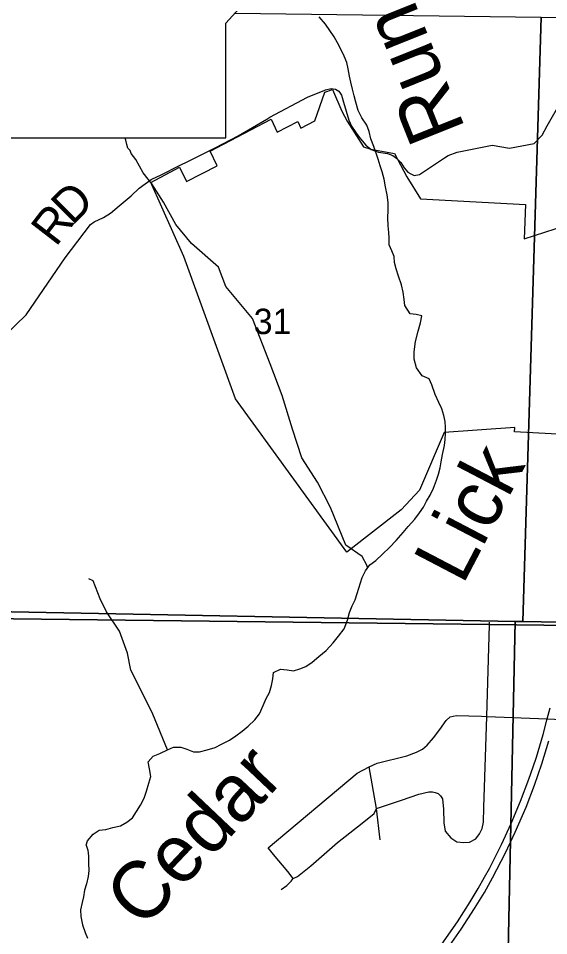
# Model space of a CAD drawing. Extents: x -19 to 40.8, y -1.8 to 26.1.
# Drawn here: x 4.466 to 5.34, y 15.443 to 16.956 of the extents above; entities that cross this region are included whole.
import ezdxf

# ---------------------------------------------------------------- set-up
doc = ezdxf.new("R2010")
doc.units = 0
for name, color, linetype in [('GM_X_City_Street', 7, 'Continuous'), ('GM_X_Corporation', 7, 'Continuous'), ('GM_X_County_Road_Text', 7, 'Continuous'), ('GM_X_Minor_River', 7, 'Continuous'), ('GM_X_Section', 7, 'Continuous'), ('GM_X_Section_Text', 7, 'Continuous'), ('GM_X_State_Route', 7, 'Continuous'), ('GM_X_Township_Road', 7, 'Continuous'), ('RW_P_Text', 7, 'Continuous'), ('SH_Text', 7, 'Continuous')]:
    doc.layers.add(name, color=color, linetype=linetype)

msp = doc.modelspace()

# ---------------------------------------------------------------- linework, layer by layer
at = {"layer": 'GM_X_City_Street'}
msp.add_lwpolyline([(5.4141, 16.267), (5.2834, 16.2739), (5.2839, 16.2809), (5.1674, 16.2728), (5.1269, 16.1777), (5.0969, 16.1455), (5.0073, 16.0756), (4.8238, 16.3283), (4.7384, 16.5632), (4.6842, 16.685), (4.7314, 16.7102), (4.7428, 16.6869), (4.7934, 16.7126), (4.7816, 16.7369), (4.8822, 16.7894), (4.8925, 16.7683), (4.9263, 16.7854), (4.9314, 16.7749), (4.9546, 16.7867), (4.9709, 16.8339), (4.9836, 16.8383), (4.9988, 16.8026), (5.0076, 16.786), (5.0348, 16.7441), (5.0466, 16.7398), (5.0857, 16.7329), (5.1062, 16.6943), (5.1288, 16.658), (5.3017, 16.6488), (5.2997, 16.5919), (5.6233, 16.6968)], dxfattribs=at)
at = {"layer": 'GM_X_Corporation'}
for points in [[(5.1684, 16.7259), (5.174, 16.7296), (5.1888, 16.7352), (5.2467, 16.7465), (5.2754, 16.7419), (5.3158, 16.7491), (5.329, 16.7629), (5.3375, 16.7783), (5.3827, 16.8572), (5.4132, 16.9039), (5.4201, 16.9126), (5.4273, 16.9192), (5.4375, 16.9273), (5.4465, 16.9319)], [(4.8753, 16.7896), (4.8803, 16.7926), (4.9421, 16.8259), (4.9708, 16.8374)], [(4.9708, 16.8374), (4.9717, 16.8378), (4.9812, 16.8399), (4.9883, 16.8389), (4.994, 16.8357), (4.9981, 16.8291), (5.0019, 16.8176), (5.0058, 16.8028), (5.0106, 16.7879), (5.0147, 16.7779), (5.0209, 16.769)], [(4.7898, 16.7422), (4.8282, 16.7618), (4.8753, 16.7896)], [(5.0209, 16.769), (5.0226, 16.7666), (5.0294, 16.7571), (5.0384, 16.7464), (5.0473, 16.7396), (5.0594, 16.7351), (5.0744, 16.7328), (5.0831, 16.7296), (5.0897, 16.7249), (5.0963, 16.7178), (5.1016, 16.7093), (5.1078, 16.7023), (5.1125, 16.6993), (5.118, 16.6968), (5.1271, 16.6983), (5.1684, 16.7259)], [(4.7463, 16.7203), (4.7801, 16.7373), (4.7898, 16.7422)], [(4.6854, 16.6904), (4.7008, 16.6979), (4.7315, 16.7129), (4.7463, 16.7203)], [(4.322, 16.3734), (4.3339, 16.3753), (4.3577, 16.3797), (4.3706, 16.3834), (4.3855, 16.3895), (4.4057, 16.4008), (4.4252, 16.4157), (4.4782, 16.4668), (4.5425, 16.5606), (4.5843, 16.6158), (4.5904, 16.6203), (4.6059, 16.6276), (4.6175, 16.6345), (4.6319, 16.6465), (4.6514, 16.663), (4.6648, 16.6758), (4.6846, 16.69), (4.6854, 16.6904)]]:
    msp.add_lwpolyline(points, dxfattribs=at)
at = {"layer": 'GM_X_Section'}
for points in [[(5.1001, 16.5044), (5.0974, 16.5164), (5.0924, 16.5304), (5.0882, 16.5428), (5.0856, 16.5533), (5.0849, 16.5628), (5.0812, 16.5726), (5.0767, 16.5823), (5.0767, 16.593), (5.0761, 16.6025), (5.0753, 16.6135), (5.0749, 16.6271), (5.0753, 16.6389), (5.0753, 16.6519), (5.0737, 16.6647), (5.071, 16.678), (5.0687, 16.6908), (5.0653, 16.7029), (5.062, 16.7127), (5.0589, 16.7236), (5.0514, 16.7446), (5.0469, 16.7571), (5.0438, 16.7691), (5.0401, 16.7796), (5.0317, 16.7919), (5.0256, 16.8039), (5.0222, 16.8175), (5.0192, 16.828), (5.0165, 16.839), (5.0139, 16.8503), (5.0113, 16.8605), (5.0094, 16.8726), (5.0072, 16.8828), (5.0027, 16.8933), (4.997, 16.9049), (4.9917, 16.9154), (4.9861, 16.9251), (4.9793, 16.9355), (4.9717, 16.9463), (4.9615, 16.9582)], [(5.0414, 16.0498), (5.0404, 16.0529), (5.0322, 16.0684), (5.0054, 16.0873), (4.9801, 16.1492), (4.9589, 16.191), (4.9332, 16.2313), (4.9176, 16.2785), (4.9004, 16.3337), (4.8806, 16.3858), (4.8516, 16.4606), (4.8076, 16.5135), (4.7953, 16.5452), (4.7508, 16.5847), (4.7252, 16.6158), (4.7046, 16.6527), (4.6855, 16.6828), (4.6712, 16.7012), (4.6594, 16.723), (4.6513, 16.7328), (4.6497, 16.7377), (4.6463, 16.7418), (4.6446, 16.7475), (4.6426, 16.7547), (4.6415, 16.7589)], [(4.5773, 15.5924), (4.5795, 15.5994), (4.5887, 15.6104), (4.5987, 15.6168), (4.6097, 15.6183), (4.6214, 15.6213), (4.6339, 15.6243), (4.6443, 15.63), (4.654, 15.6375), (4.6605, 15.6476), (4.667, 15.6581), (4.6731, 15.6697), (4.6769, 15.6816), (4.6807, 15.6943), (4.6842, 15.7058), (4.6819, 15.7182), (4.6796, 15.7296), (4.688, 15.7393), (4.6986, 15.7435), (4.7117, 15.7496), (4.7214, 15.7537), (4.7336, 15.7541), (4.7432, 15.7506), (4.7543, 15.7464), (4.7642, 15.7463), (4.7771, 15.7498), (4.7902, 15.7536), (4.8007, 15.7589), (4.8134, 15.7657), (4.8239, 15.7725), (4.8343, 15.7805), (4.8446, 15.7888), (4.8557, 15.799), (4.863, 15.8091), (4.869, 15.8226), (4.8744, 15.8342), (4.8794, 15.8442), (4.8828, 15.8557), (4.8851, 15.8668), (4.886, 15.8768), (4.8976, 15.8828), (4.9086, 15.8816), (4.9193, 15.8797), (4.9295, 15.8831), (4.9393, 15.8872), (4.9497, 15.894), (4.9612, 15.9035), (4.973, 15.9133), (4.9848, 15.9259), (4.9936, 15.9368), (5.0027, 15.9489), (5.008, 15.9631), (5.0114, 15.9758), (5.016, 15.9869), (5.0206, 15.997), (5.0244, 16.0073), (5.0324, 16.0338), (5.0377, 16.0446), (5.045, 16.0544), (5.0547, 16.0615), (5.0661, 16.0721), (5.0772, 16.0831), (5.0882, 16.0945), (5.1, 16.1078), (5.1084, 16.1176), (5.119, 16.1301), (5.1271, 16.1402), (5.1333, 16.1499), (5.1383, 16.1596), (5.1444, 16.1693), (5.1498, 16.1812), (5.155, 16.1943), (5.1585, 16.2043), (5.1609, 16.2143), (5.1629, 16.2242), (5.1647, 16.2368), (5.1681, 16.2514), (5.1693, 16.2613), (5.1697, 16.2712), (5.1698, 16.2811), (5.1691, 16.291), (5.1673, 16.3008), (5.1635, 16.3117), (5.1586, 16.3222), (5.1525, 16.3357), (5.1471, 16.3515), (5.1426, 16.3612), (5.1314, 16.3662), (5.1222, 16.3796), (5.1184, 16.3939), (5.118, 16.4061), (5.1205, 16.4229), (5.1249, 16.4398), (5.1286, 16.4536), (5.1309, 16.4654), (5.1214, 16.4674), (5.1118, 16.4686), (5.103, 16.4824), (5.1016, 16.4922), (5.1001, 16.5044)], [(4.7117, 15.7496), (4.6875, 15.8084), (4.6683, 15.8472), (4.6511, 15.8807), (4.6456, 15.9091), (4.6325, 15.9454), (4.6108, 15.977), (4.6002, 15.9984), (4.5891, 16.0283), (4.5818, 16.0316)], [(4.5773, 15.5924), (4.5802, 15.5839), (4.5812, 15.574), (4.5814, 15.5619), (4.582, 15.5505), (4.5807, 15.5406), (4.5779, 15.5283), (4.5747, 15.5184), (4.5727, 15.5073), (4.571, 15.4978), (4.5682, 15.4856), (4.5688, 15.4746), (4.5713, 15.4609), (4.5758, 15.4485), (4.5798, 15.4387)]]:
    msp.add_lwpolyline(points, dxfattribs=at)
at = {"layer": 'GM_X_State_Route'}
for points in [[(4.3769, 16.7589), (4.3704, 16.384), (4.3644, 15.9666), (5.2419, 15.956), (5.3769, 15.9544), (5.3823, 15.9544), (5.3878, 15.9543), (5.57, 15.952), (6.2458, 15.936), (6.5861, 15.9329), (6.6409, 15.9314), (6.7023, 15.9297), (6.805, 15.9268), (6.9672, 15.9223), (6.993, 15.9217), (6.9993, 15.9207), (7.1288, 15.9169)], [(7.1288, 15.9169), (6.9993, 15.9207), (6.993, 15.9217), (6.9672, 15.9223), (6.805, 15.9268), (6.7023, 15.9297), (6.6409, 15.9314), (6.5861, 15.9329), (6.2458, 15.936), (5.57, 15.952), (5.3878, 15.9543), (5.3823, 15.9544), (5.3769, 15.9544), (5.2419, 15.956), (4.3644, 15.9666), (4.3628, 15.868), (4.3494, 15.3211)], [(4.8988, 15.519), (4.9083, 15.526), (4.9151, 15.5327), (4.9189, 15.5374), (4.9259, 15.5408), (4.9477, 15.5585), (4.9915, 15.5965), (5.0322, 15.6288), (5.052, 15.6445), (5.0562, 15.6529), (5.097, 15.6665), (5.1261, 15.6767), (5.1421, 15.6804), (5.1482, 15.6805), (5.1529, 15.6793), (5.1575, 15.6775), (5.1616, 15.6739), (5.1651, 15.6685), (5.1664, 15.6518), (5.1669, 15.6289), (5.1693, 15.6156), (5.1784, 15.6045), (5.1884, 15.5979), (5.1998, 15.5966), (5.2096, 15.5975), (5.22, 15.6028), (5.2256, 15.611), (5.2303, 15.6199), (5.2322, 15.63), (5.2332, 15.6544), (5.2377, 15.8045), (5.2421, 15.9555), (5.2422, 15.96)], [(4.8774, 15.5881), (5.0244, 15.7113), (5.0439, 15.7213), (5.0572, 15.7274), (5.1059, 15.7394), (5.1221, 15.7456), (5.1318, 15.7506), (5.1396, 15.7574), (5.1502, 15.7695), (5.1602, 15.7829), (5.1711, 15.7981), (5.1775, 15.8041), (5.1873, 15.8064), (5.229, 15.8048)], [(5.229, 15.8048), (5.2377, 15.8045), (5.3375, 15.8009), (5.3497, 15.8003), (5.3849, 15.7991)], [(5.062, 15.6011), (5.0562, 15.6529), (5.0439, 15.7213)], [(4.9189, 15.5374), (4.9099, 15.5487), (4.886, 15.5771), (4.8774, 15.5881)]]:
    msp.add_lwpolyline(points, dxfattribs=at)
at = {"layer": 'GM_X_Township_Road'}
for points in [[(5.1635, 15.429), (5.1894, 15.4661), (5.2105, 15.4987), (5.2235, 15.5206), (5.2342, 15.5395), (5.2421, 15.554), (5.2622, 15.5932), (5.2781, 15.6279), (5.2937, 15.6648), (5.3073, 15.701), (5.3145, 15.7217), (5.3196, 15.7374), (5.3308, 15.7748), (5.3375, 15.8009), (5.3421, 15.8189)], [(5.1646, 15.41), (5.1956, 15.4536), (5.2177, 15.4878), (5.2339, 15.5144), (5.2475, 15.5386), (5.2689, 15.5797), (5.2848, 15.6135), (5.3028, 15.6549), (5.3165, 15.6912), (5.3288, 15.7264), (5.3403, 15.7641)]]:
    msp.add_lwpolyline(points, dxfattribs=at)
at = {"layer": 'RW_P_Text'}
msp.add_lwpolyline([(4.8227, 16.9645), (5.3277, 16.9579), (5.2973, 15.9612), (5.2848, 15.9609), (4.3678, 15.9788), (4.3772, 16.7589)], dxfattribs=at)
for points in [[(6.3345, 16.9403), (6.2953, 15.9429), (5.2973, 15.9612), (5.3277, 16.9579)], [(4.3678, 15.9788), (5.2848, 15.9609), (5.2615, 14.8764), (4.3391, 14.8802), (4.3635, 15.8676)], [(5.2973, 15.9612), (6.2953, 15.9429), (6.2831, 14.8757), (5.2615, 14.8764), (5.2848, 15.9609)]]:
    msp.add_lwpolyline(points, close=True, dxfattribs=at)
at = {"layer": 'SH_Text'}
for p, q in [((4.8076, 16.7589), (4.8076, 16.9478)), ((2.7742, 16.7589), (4.8076, 16.7589))]:
    msp.add_line(p, q, dxfattribs=at)
msp.add_lwpolyline([(4.8076, 17.2367), (5.4357, 17.6388), (4.8076, 16.9478)], dxfattribs=at)

# ---------------------------------------------------------------- texts
at = {"layer": 'GM_X_County_Road_Text'}
for s, rotation, p in [('D', 44.9794, (4.5546, 16.6131)), ('R', 52.3362, (4.5274, 16.5776))]:
    msp.add_text(s, height=0.0568, rotation=rotation, dxfattribs=at).set_placement(p)
at = {"layer": 'GM_X_Minor_River'}
for s, height, rotation, p in [('Run', 0.09467, 111.8301, (5.2032, 16.7735)), ('Lick', 0.09467, 62.401, (5.198, 16.0197)), ('Cedar', 0.09468, 46.5505, (4.67, 15.4519))]:
    msp.add_text(s, height=height, rotation=rotation, dxfattribs=at).set_placement(p)
at = {"layer": 'GM_X_Section_Text'}
msp.add_text('31', height=0.04186, rotation=0, dxfattribs=at).set_placement((4.8536, 16.4351))

doc.saveas('drawing.dxf')
